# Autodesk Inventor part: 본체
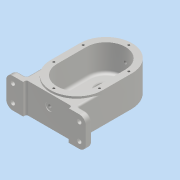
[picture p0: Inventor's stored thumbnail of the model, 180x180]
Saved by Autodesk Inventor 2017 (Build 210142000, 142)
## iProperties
Part Number: 본체
Material: 알루미늄 6061
Document SubType Name: Modeling
Designer: MRC
Density: 2.7 g/cm^3
Appearance: 알루미늄 - 평지
Mass: 754.253 g
Surface Area: 584.291 cm^2
Volume: 279.353 cm^3
Author: MRC
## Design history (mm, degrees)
sketch "스케치1"
  geometry: L1 (0, 0)-(0, -45); L2 (-40, 0)-(-40, -45); L3 (40, -45)-(40, 0); L4 (0, 0)-(0, -45); L5 (-61, -92)-(61, -92); L6 (61, -92)-(61, -82); L7 (61, -82)-(40, -82); L8 (40, -82)-(40, -45); L9 (-61, -92)-(-61, -82); L10 (-61, -82)-(-40, -82); L11 (-40, -82)-(-40, -45); A1 r 40 centre (0, 0) between (40, 0) and (-40, 0); A2 r 40 centre (0, -45) between (-40, -45) and (40, -45); 2 further points
  constraints: 26 end point, 6 point on circle, 4 perpendicular, 4 tangent, 3 parallel, 3 point on line, 2 centre point, 2 midpoint, 1 horizontal, 1 vertical, 1 other
  dimensions: "d0" = 45 distance of L1.start L1.end; "d1" = 80 distance between parallel lines of L3 L2; "d17" = 10 distance of L5.end L6.end; "d18" = 122 distance of L5.start L5.end; "d19" = 92 distance from line of L5 L1.start; "d20" = 37 distance of L10.end L11.end
extrude "돌출1" new body sketch "스케치1" stored distance "d4" = 49; taper "d5" = 0 deg
sketch "스케치2"
  geometry: L1 (0, 0)-(0, -45); L2 (-30, 0)-(-30, -45); L3 (30, -45)-(30, 0); A1 r 40 centre (0, -45) between (-40, -45) and (40, -45) reference; A2 r 40 centre (0, 0) between (40, 0) and (-40, 0) reference; A3 r 30 centre (0, 0) between (30, 0) and (-30, 0); A4 r 30 centre (0, -45) between (-30, -45) and (30, -45); 1 further point
  constraints: 8 end point, 4 point on circle, 4 tangent, 2 centre point, 1 midpoint, 1 parallel, 1 vertical
  dimensions: "d6" = 10 radial gap between concentric circles of A1 A4; "d7" = 30 radius of A3
extrude "돌출2" cut sketch "스케치2" distance "d8" = 41; taper "d9" = 0 deg
sketch "스케치3"
  geometry: L1 (0, 0)-(0, -45); L2 (-26, 0)-(-26, -45); L3 (26, -45)-(26, 0); A1 r 40 centre (0, 0) between (40, 0) and (-40, 0) reference; A2 r 40 centre (0, -45) between (-40, -45) and (40, -45) reference; A3 r 26 centre (0, 0) between (26, 0) and (-26, 0); A4 r 26 centre (0, -45) between (-26, -45) and (26, -45); 1 further point
  constraints: 8 end point, 4 point on circle, 4 tangent, 2 centre point, 1 midpoint, 1 parallel, 1 vertical
  dimensions: "d10" = 52 distance between parallel lines of L3 L2
extrude "돌출3" join sketch "스케치3" distance "d11" = 11; taper "d12" = 0 deg
sketch "스케치4"
  geometry: L1 (-26, 0)-(-26, -45) reference; L2 (26, -45)-(26, 0) reference; L3 (-26, -30)-(26, -30); A1 r 26 centre (0, 0) between (26, 0) and (-26, 0) reference
  constraints: 2 end point, 2 point on line, 1 perpendicular
  dimensions: "d13" = 30 distance from line of A1.centre L3
extrude "돌출4" cut sketch "스케치4" distance "d14" = 3; taper "d15" = 0 deg
sketch "스케치5"
  geometry: L1 (-61, -82)-(-61, -92); L2 (-61, -92)-(61, -92); L3 (61, -92)-(61, -82); L4 (61, -82)-(40, -82); L5 (40, -82)-(40, -45); L6 (-61, -82)-(-40, -82); L7 (-40, -82)-(-40, -45); L8 (0, 0)-(0, -45); A1 r 26 centre (0, 0) between (26, 0) and (-26, 0) reference; A2 r 40 centre (0, 0) between (40, 0) and (-40, 0) reference; A3 r 40 centre (0, -45) between (-40, -45) and (40, -45) reference
  constraints: 16 end point, 5 perpendicular, 2 vertical, 1 horizontal, 1 point on circle, 1 other
  dimensions: "d21" = 122 distance of L1.end L2.end; "d22" = 10 distance of L2.end L3.end; "d23" = 10 distance of L1.start L1.end; "d24" = 92 distance from line of A1.centre L2; "d25" = 37 distance of L4.end L5.end
extrude "돌출5" join sketch "스케치5" distance "d26" = 46; taper "d27" = 0 deg
sketch "스케치6"
  geometry: C1 r 14 at (0, 0); C2 r 11 at (0, 0); A1 r 26 centre (0, 0) between (26, 0) and (-26, 0) reference
  constraints: 2 centre point, 2 coincident
  dimensions: "d28" = 28 diameter of C1; "d29" = 22 diameter of C2
extrude "돌출6" cut sketch "스케치6" distance "d30" = 4; taper "d31" = 0 deg
sketch "스케치7"
  geometry: A1 r 30 centre (0, -45) between (-30, -45) and (30, -45) reference; 1 further point
  constraints: 1 coincident
hole "구멍1" sketch "스케치7" at (0, -45) diameter "d32" = 20; stored, may be unused: countersink angle "d36" = 90 deg, drill point angle "d38" = 0 deg; dims "d33" = 6, "d34" = 28, "d35" = 8, "d37" = 12
sketch "스케치8"
  geometry: C1 r 14 at (0, 0); A1 r 30 centre (0, 0) between (30, 0) and (-30, 0) reference
  constraints: 1 centre point, 1 coincident
  dimensions: "d39" = 28 diameter of C1
extrude "돌출7" cut sketch "스케치8" distance "d40" = 8; taper "d41" = 0 deg
sketch "스케치9"
  geometry: C1 r 14 at (0, 0) reference; C2 r 11 at (0, 0)
  constraints: 1 centre point, 1 coincident
  dimensions: "d42" = 22 diameter of C2
extrude "돌출8" cut sketch "스케치9" stored distance "d43" = 8; taper "d44" = 0 deg
sketch "스케치10"
  geometry: A1 r 30 centre (0, 0) between (30, 0) and (-30, 0) reference; 1 further point
  constraints: 1 vertical alignment
  dimensions: "d45" = 35 distance of A1.centre point (0, 35)
hole "구멍2" sketch "스케치10" at (0, 35) diameter "d46" = 3.242; stored, may be unused: countersink angle "d50" = 90 deg, drill point angle "d52" = 118 deg; dims "d47" = 8, "d48" = 28, "d49" = 8, "d51" = 10
sketch "스케치11"
  geometry: A1 r 30 centre (0, -45) between (-30, -45) and (30, -45) reference; A2 r 30 centre (0, 0) between (30, 0) and (-30, 0) reference; 1 further point
  constraints: 1 vertical alignment
  dimensions: "d56" = 35 distance of A1.centre point (0, -80)
hole "구멍3" sketch "스케치11" at (0, -80) diameter "d57" = 3.242; stored, may be unused: countersink angle "d61" = 90 deg, drill point angle "d63" = 118 deg; dims "d58" = 8, "d59" = 28, "d60" = 8, "d62" = 10
sketch "스케치12"
  geometry: L1 (-61, -92)-(61, -92) reference; L2 (-35, -92)-(35, -92); L3 (35, -92)-(35, -87); L4 (35, -87)-(-35, -87); L5 (-35, -87)-(-35, -92); A1 r 40 centre (0, -45) between (-40, -45) and (40, -45) reference; 2 further points
  constraints: 8 end point, 2 parallel, 1 collinear, 1 horizontal, 1 midpoint, 1 perpendicular, 1 vertical alignment
  dimensions: "d67" = 70 distance between parallel lines of L3 L5; "d68" = 5 distance between parallel lines of L1 L4
extrude "돌출9" cut sketch "스케치12" stored distance "d69" = 8; taper "d70" = 0 deg
sketch "스케치13"
  geometry: C1 r 14 at (0, 0) reference; 1 further point
  constraints: 1 vertical alignment
  dimensions: "d71" = 20 distance of C1.centre point (0, 20)
hole "구멍4" sketch "스케치13" at (0, 20) diameter "d72" = 3.242; stored, may be unused: countersink angle "d76" = 90 deg, drill point angle "d78" = 118 deg; dims "d73" = 8, "d74" = 28, "d75" = 8, "d77" = 10
node "작업 평면1"
sketch "스케치14"
  geometry: L1 (40, 24.5)-(-40, 24.5) reference; C1 r 6 at (0, 3.5); 1 further point
  constraints: 1 centre point, 1 vertical alignment
  dimensions: "d83" = 12 diameter of C1; "d84" = 21 distance from line of L1 C1.centre
extrude "돌출10" join sketch "스케치14" stored distance "d85" = 8; taper "d86" = 0 deg
hole "구멍5" diameter "d89" = 4.917; stored, may be unused: countersink angle "d93" = 90 deg, drill point angle "d95" = 118 deg; dims "d87" = 10, "d88" = 10, "d90" = 12, "d91" = 28, "d92" = 8, "d94" = 17.1
sketch "스케치15"
  geometry: L1 (75, 3)-(-5, 3) reference; C1 r 6 at (35, -18); 1 further point
  constraints: 1 centre point, 1 vertical alignment
  dimensions: "d96" = 12 diameter of C1; "d97" = 21 distance from line of L1 C1.centre
extrude "돌출11" cut sketch "스케치15" distance "d98" = 1; taper "d99" = 0 deg
hole "구멍6" diameter "d102" = 4.917; stored, may be unused: countersink angle "d106" = 90 deg, drill point angle "d108" = 118 deg; dims "d100" = 10, "d101" = 10, "d103" = 12, "d104" = 28, "d105" = 8, "d107" = 17.1
fillet "모깎기1" dims "d109" = 10, "d110" = 3, "d128" = 5
fillet "모깎기2" dims "d111" = 3
sketch "스케치16"
  geometry: C1 r 5.5 at (8, 7); C2 r 3.3 at (8, 7); C3 r 5.5 at (8, 33); C4 r 3.3 at (8, 33); A1 r 7 centre (8, 7) between (8, 0) and (15, 7) reference; A2 r 7 centre (8, 33) between (15, 33) and (8, 40) reference; 1 further point
  constraints: 4 centre point, 4 coincident
  dimensions: "d112" = 11 diameter of C1; "d113" = 6.6 diameter of C2; "d118" = 11 diameter of C3; "d119" = 6.6 diameter of C4
extrude "돌출12" cut sketch "스케치16" distance "d114" = 2; taper "d115" = 0 deg
extrude "돌출13" cut sketch "스케치16" stored distance "d116" = 2; taper "d117" = 0 deg
chamfer "모따기1" distance "d120" = 1; stored, may be unused: second distance "d121" = 2, angle "d122" = 45 deg
fillet "모깎기3" dims "d123" = 3, "d124" = 0.3
sketch "스케치17"
  geometry: L1 (-51, -92)-(-35, -92) reference; A1 r 37 centre (0, 0) between (37, 0) and (-37, 0) reference; 1 further point
  constraints: 1 vertical alignment, 1 other
  dimensions: "d125" = 12 distance from line of L1 point (0, -80)
feature "엠보싱1" sketch "스케치17" dims "d0" = 45, "d1" = 80, "d17" = 10, "d18" = 122, "d19" = 92, "d20" = 37, "d126" = 0.5, "d127" = 0
node "솔리드1"
pattern_circular "원형 패턴1" dims angle "d54" = 180 deg
pattern_circular "원형 패턴2" dims angle "d65" = 180 deg
pattern_circular "원형 패턴3" dims angle "d80" = 360 deg
mirror "미러1"
other parameters: "d82" = 43
